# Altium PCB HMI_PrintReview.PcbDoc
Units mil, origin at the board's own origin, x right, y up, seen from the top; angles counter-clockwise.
Board outline 3135 x 2040 mil, 2 copper layers (Top Layer, Bottom Layer); 24 components, 26 nets, 141 pads, 13 vias.
Unrouted connection lines stored in the file: 1.
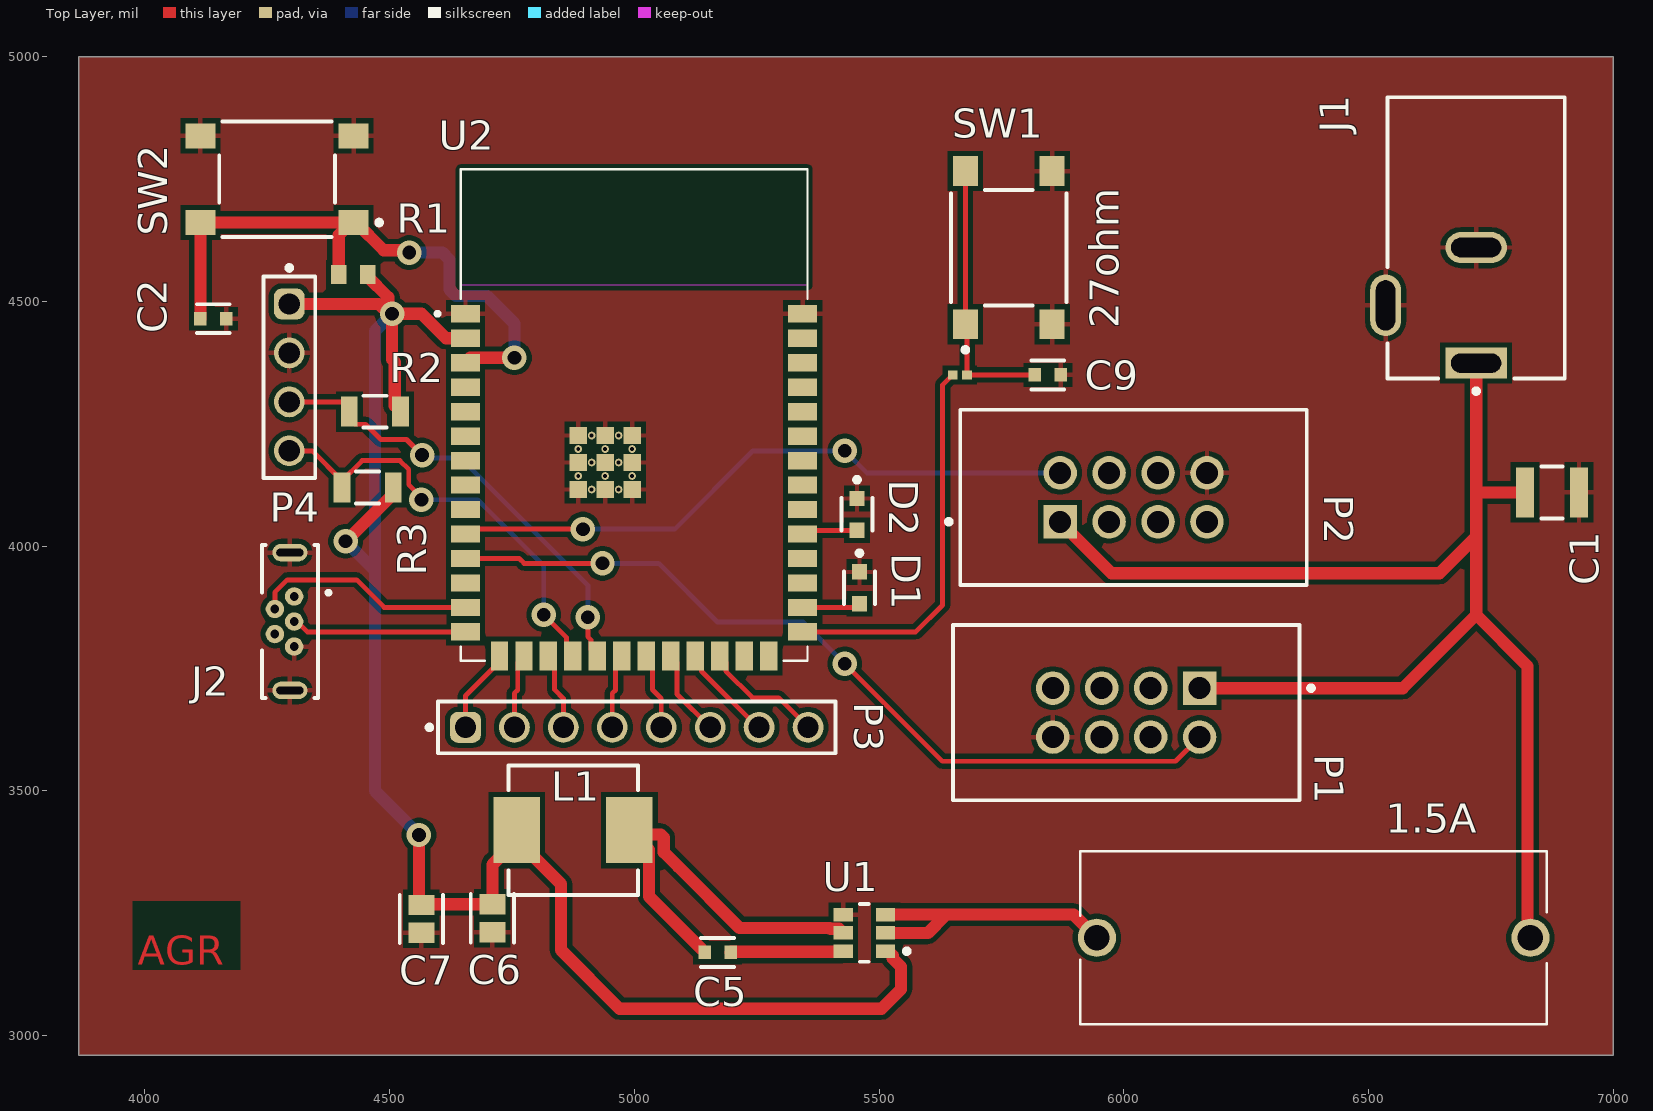
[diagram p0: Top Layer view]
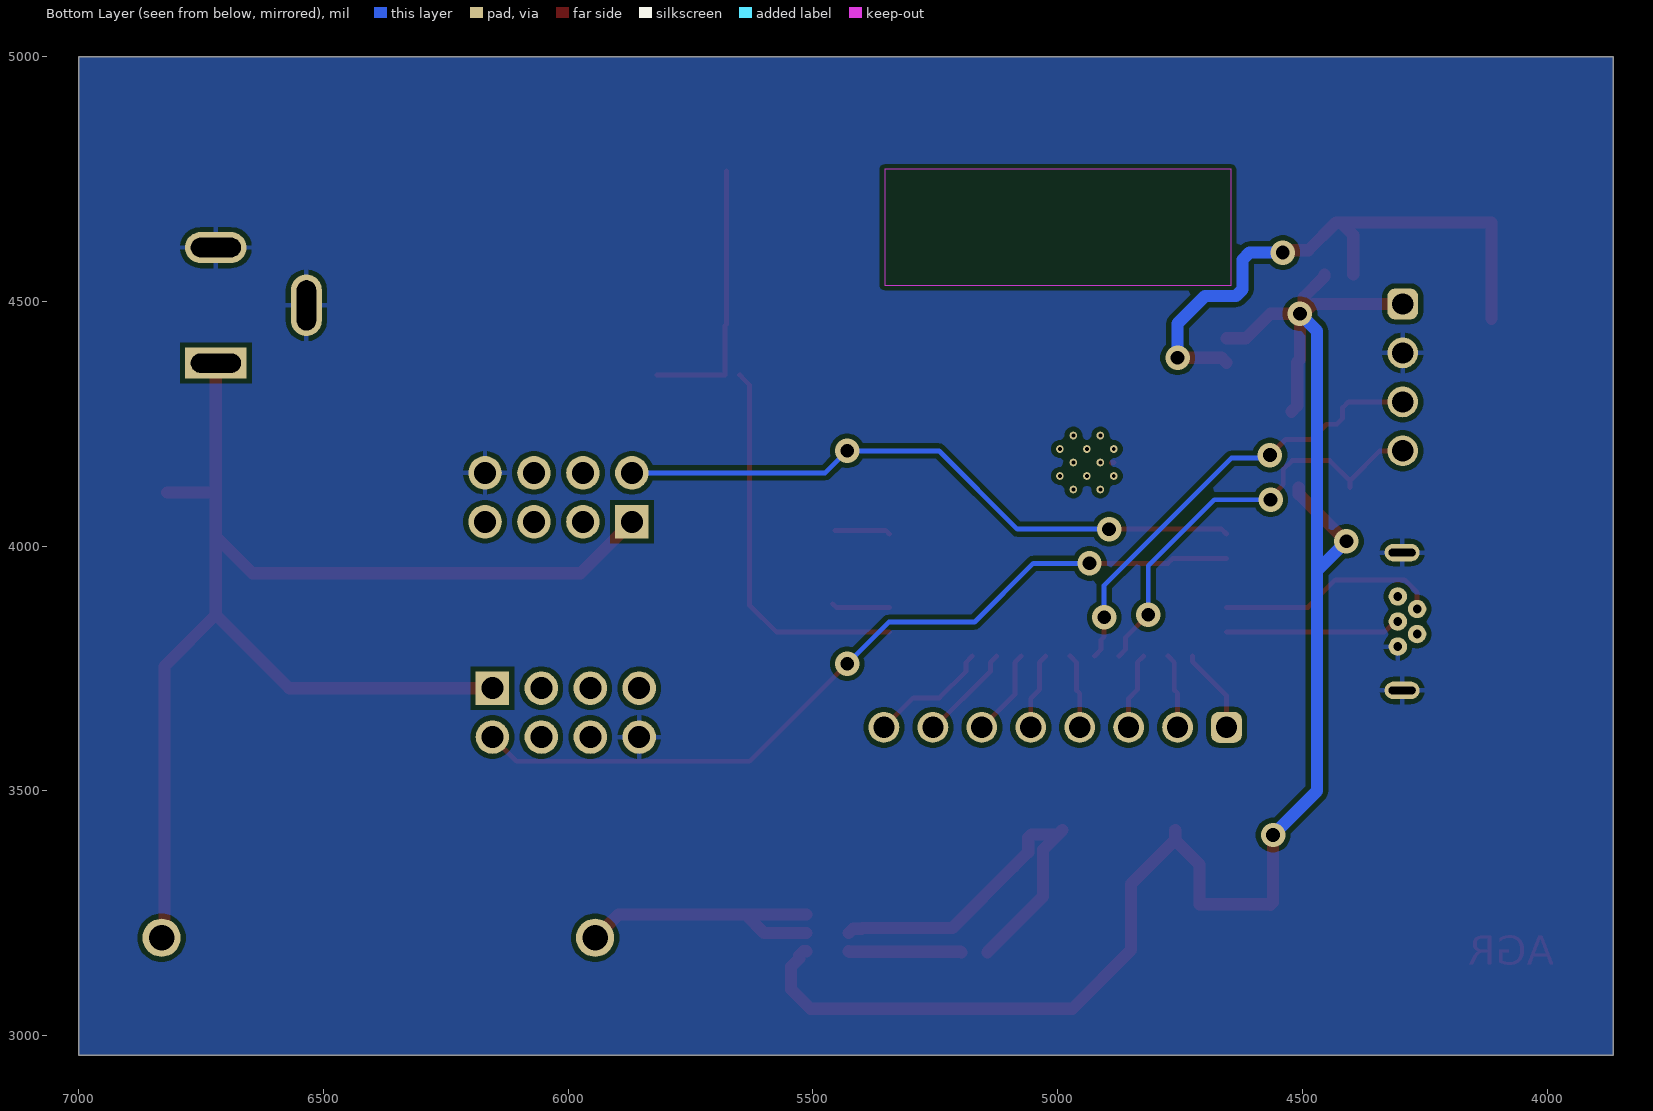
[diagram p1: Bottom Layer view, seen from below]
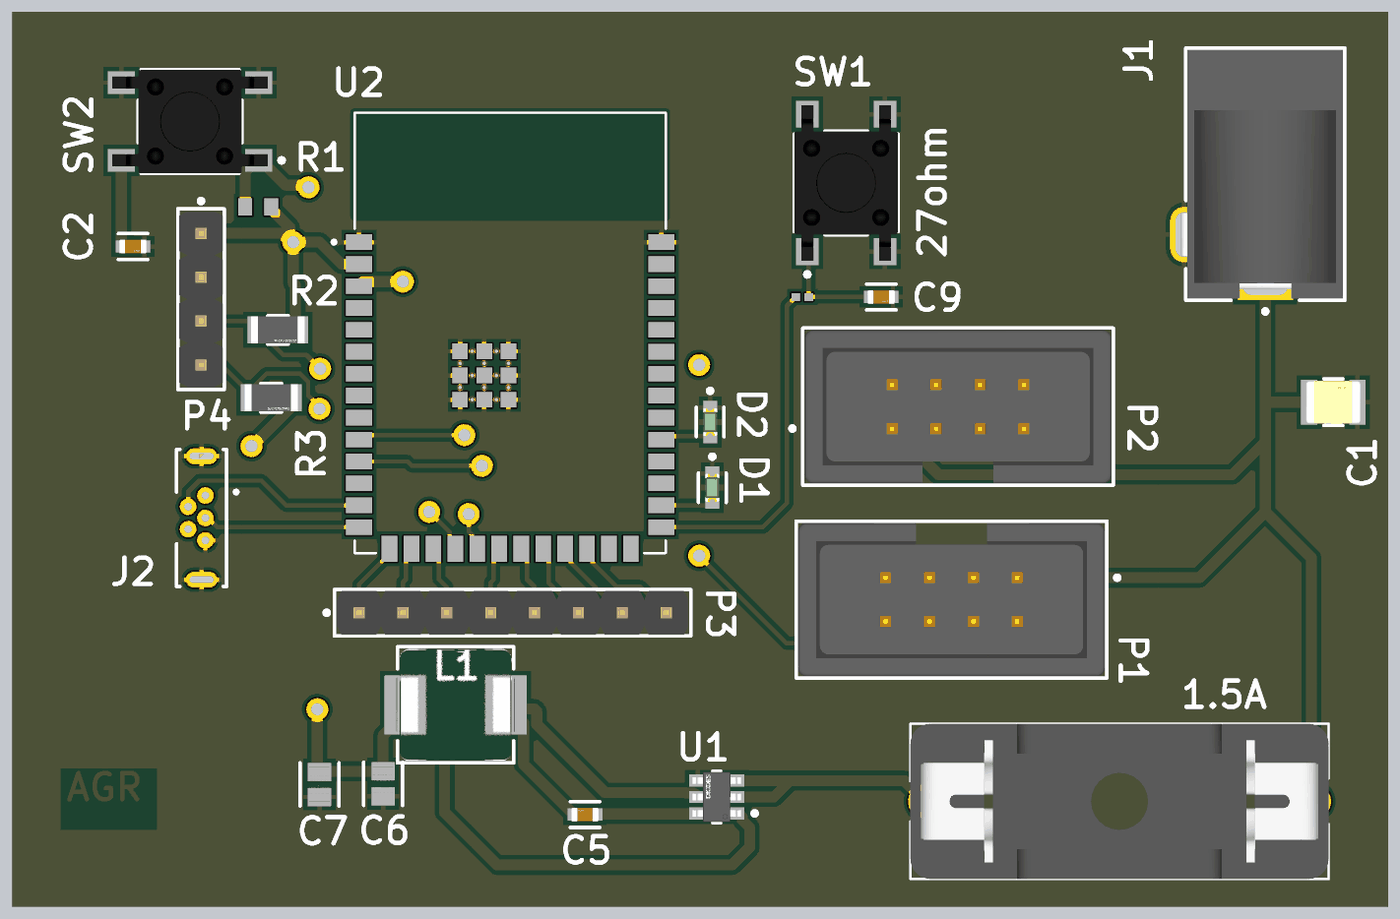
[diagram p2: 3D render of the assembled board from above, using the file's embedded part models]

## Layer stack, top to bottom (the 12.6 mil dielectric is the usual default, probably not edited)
Top Solder: solder mask 0.4, Solder Resist, Dk 3.5
Top Layer: signal copper 1.4
Dielectric 1: dielectric 12.6, FR-4, Dk 4.8
Bottom Layer: signal copper 1.4
Bottom Solder: solder mask 0.4, Solder Resist, Dk 3.5

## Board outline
3865,2960 3865,5000 7000,5000 7000,2960

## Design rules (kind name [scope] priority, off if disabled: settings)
Clearance [All] p1: gap=10 ignorepadtopadclearanceinfootprint=FALSE
PolygonConnect [All] p1: connectstyle=Relief reliefconductorwidth=10 reliefentries=4 polygonreliefangle="90 Angle" airgapwidth=10
RoutingVias [All] p1: holewidth=28 width=50 viastyle="Through Hole" minholewidth=28 minwidth=50 maxholewidth=28 maxwidth=50
SolderMaskExpansion [All] p1: expansion=4 istentingtop=FALSE
SupplyNets "Schematic Supply Nets_1" [InNet('GND')] p1: voltage=0.000
SupplyNets "Schematic Supply Nets" [InNet('+3.3')] p2: voltage=0.000
Width [All] p1: maxlimit=10 minlimit=10 preferedwidth=10
30 further rules are at their usual default settings.

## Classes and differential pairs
net class GND: GND

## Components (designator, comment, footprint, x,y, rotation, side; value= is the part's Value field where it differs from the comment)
1.5A "4628" 4628-Footprint-1 6830.83,3200 r180 top
27ohm "RC0402FR-0727RL" RESC1005X40X25LL05T10 5665,4350 r180 top
C1 "10uF" FP-C1210C106M6PACTU-MFG 6875,4110 r0 top
C2 "GRM188R72A104KA35D" FP-GRM188-0_1-e0_2_0_5-MFG 4140,4465 r0 top
C5 "GRM188R72A104KA35D" FP-GRM188-0_1-e0_2_0_5-MFG 5170,3170 r180 top
C6 "CL21A226MOCLRNC" FP-CL21-IPC_C 4710,3240 r270 top
C7 "CL21A226MOCLRNC" FP-CL21-IPC_C 4565,3238.57 r270 top
C9 "GRM188R72A104KA35D" FP-GRM188-0_1-e0_2_0_5-MFG 5845,4350 r0 top
D1 "SML-D12U8WT86C" FP-SML-D12-MFG 5460,3915 r270 top
D2 "SML-D12U8WT86C" FP-SML-D12-MFG 5455,4065 r270 top
J1 "PJ-102A" FP-PJ-102A-MFG 6720,4630 r0 top
J2 "USB3131-30-0230-A_REVB" GCT_USB3131-30-0230-A_REVB 4296.34,3846.18 r270 top
L1 "4.7uH" FP-IHLP-2525EZ-FP_2_413x3-MFG 4875,3420 r180 top
P1 "70246-0801" FP-0702460801-MFG 6005,3660 r180 top
P2 "70246-0801" FP-0702460801-MFG 6020,4100 r0 top
P3 "Conn 01x08" 61300811121 5005,3630 r0 top
P4 "01x04" 61300411121 4295,4345 r270 top
R1 "RC0603JR-0710KL" RESC1608X55X25ML10T15 4425.47,4555 r0 top
R2 "10k 0.25W" FP-CR1206-IPC_C 4470,4275 r0 top value=10kR
R3 "10k 0.25W" FP-CR1206-IPC_C 4455,4120 r0 top value=10kR
SW1 "PTS645SH50SMTR92LFS" FP-PTS645SH50SMTR92LFS-MFG 5765,4610 r90 top
SW2 "PTS645SH50SMTR92LFS" FP-PTS645SH50SMTR92LFS-MFG 4270,4750 r180 top
U1 "AP63203WU-7" FP-TSOT26-MFG 5470,3210 r180 top
U2 "ESP32-S3-WROOM-1-N4" XCVR_ESP32-S3-WROOM-1-N4 4999.49,4267.91 r0 top

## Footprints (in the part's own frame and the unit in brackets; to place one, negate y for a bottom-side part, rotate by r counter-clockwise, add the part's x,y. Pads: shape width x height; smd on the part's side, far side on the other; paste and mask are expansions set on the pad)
4628-Footprint-1 [mm]
  round 1.98 hole 1.32: 1(0,0) 2(22.5,0)
  silkscreen extent -0.85,-4.49 23.36,4.49, body extent -0.85,-4.5 23.35,4.5, height 11.99
61300411121 [mm] "Pin Header, pitch 2.54 mm, THT, Vertical, single row, 4p"
  rrect50% 1.6x1.6 hole 1.1: 1(-3.81,0)
  round 1.6 hole 1.1: 2(-1.27,0) 3(1.27,0) 4(3.81,0)
  silkscreen extent -5.8,-1.35 5.23,1.35, body extent -5.08,-1.27 5.08,1.27, height 8.57
61300811121 [mm] "Pin Header, pitch 2.54 mm, THT, Vertical, single row, 8p"
  rrect50% 1.6x1.6 hole 1.1: 1(-8.89,0)
  round 1.6 hole 1.1: 2(-6.35,0) 3(-3.81,0) 4(-1.27,0) 5(1.27,0) 6(3.81,0) 7(6.35,0) 8(8.89,0)
  silkscreen extent -10.88,-1.35 10.31,1.35, body extent -10.16,-1.27 10.16,1.27, height 8.57
FP-0702460801-MFG [mm]
  rect 1.74x1.74 hole 1.14 paste-2539.97 mask+0: 1(-3.81,-1.27)
  round 1.74 hole 1.14 paste-2539.97 mask+0: 2(-3.81,1.27) 3(-1.27,-1.27) 4(-1.27,1.27) 5(1.27,-1.27) 6(1.27,1.27) 7(3.81,-1.27) 8(3.81,1.27)
  silkscreen extent -9.72,-4.54 8.99,4.54, body extent -9.09,-4.64 9.09,4.64, height 0.25
FP-C1210C106M6PACTU-MFG [mm]
  rect 0.95x2.6 smd paste+0 mask+0: 1(-1.4,0) 2(1.4,0)
  silkscreen extent -0.55,-1.35 0.55,1.35, body extent -1.97,-1.45 1.97,1.45, height 0.25
FP-CL21-IPC_C [mil]
  rect 41.52x53.39 smd paste+0 mask+0: 1(-28.57,0) 2(28.57,0)
  silkscreen extent -49,-44 49,44, body extent -53,-32 53,32, height 10
FP-CR1206-IPC_C [mil]
  rect 33.79x61.5 smd paste+0 mask+0: 1(-52.24,0) 2(52.24,0)
  silkscreen extent -24,-32 24,32, body extent -73,-36 73,36, height 10
FP-GRM188-0_1-e0_2_0_5-MFG [mm]
  rect 0.65x0.7 smd paste+0 mask+0: 1(-0.675,0) 2(0.675,0)
  silkscreen extent -0.85,-0.75 0.85,0.75, body extent -1.1,-0.55 1.1,0.55, height 0.25
FP-IHLP-2525EZ-FP_2_413x3-MFG [mil]
  rect 95x135 smd paste+0 mask+0: 1(-115,0) 2(115,0)
  silkscreen extent -132,-132 132,132, body extent -166,-136 166,136, height 10
FP-PJ-102A-MFG [mm]
  rect 3.2x1.6 hole 1 slot 2.6 at 0 deg paste-2539.97 mask+0: 1(0,-6.5)
  rrect100% 3.2x1.6 hole 1 slot 2.6 at 0 deg paste-2539.97 mask+0: 2(0,-0.5)
  rrect100% 1.6x3.2 hole 2.6 slot 1 at 0 deg paste-2539.97 mask+0: 3(-4.7,-3.5)
  silkscreen extent -4.6,-8.07 4.6,7.3, body extent -5.6,-7.4 4.7,7.4, height 0.25
FP-PTS645SH50SMTR92LFS-MFG [mm]
  rect 1.55x1.3 smd paste+0 mask+0: 1(-3.975,2.25) 2(3.975,2.25) 3(-3.975,-2.25) 4(3.975,-2.25)
  silkscreen extent -5.42,-3 3,3, body extent -4.85,-3.1 4.85,3.1, height 0.25
FP-SML-D12-MFG [mm]
  rect 0.8x0.8 smd paste+0 mask+0: 1(-0.825,0) 2(0.825,0)
  silkscreen extent -1.92,-0.8 0.85,0.8, body extent -1.33,-0.55 1.33,0.55, height 0.25
FP-TSOT26-MFG [mm]
  rect 1x0.7 smd paste+0 mask+0: 1(-1.099,0.95) 2(-1.099,0) 3(-1.099,-0.95) 4(1.099,-0.95) 5(1.099,0) 6(1.099,0.95)
  silkscreen extent -2.33,-1.5 0.22,1.5, body extent -1.7,-1.6 1.7,1.6, height 0.25
GCT_USB3131-30-0230-A_REVB [mm]
  round 0.958 hole 0.45: 1(-1.3,0.22) 2(-0.65,-0.78) 3(0,0.22) 4(0.65,-0.78) 5(1.3,0.22)
  oval 0.908x1.816 hole 0.4 slot 1.4 at 90 deg: S1(-3.575,0) S2(3.575,0)
  silkscreen extent -3.97,-1.45 3.97,2.1
RESC1005X40X25LL05T10 [mm] "Chip Resistor, 2-Leads, Body 1.00x0.50mm, IPC High Density"
  rect 0.5x0.45 smd: 1(-0.375,0) 2(0.375,0)
  body extent -0.53,-0.27 0.53,0.28, height 0.4
RESC1608X55X25ML10T15 [mm] "Chip Resistor, 2-Leads, Body 1.60x0.80mm, IPC Low Density"
  rect 0.8x1 smd: 1(-0.75,0) 2(0.75,0)
  body extent -0.85,-0.45 0.85,0.45, height 0.55
XCVR_ESP32-S3-WROOM-1-N4 [mm]
  rect 1.5x0.9 smd: 1(-8.75,5.26) 2(-8.75,3.99) 3(-8.75,2.72) 4(-8.75,1.45) 5(-8.75,0.18) 6(-8.75,-1.09) 7(-8.75,-2.36) 8(-8.75,-3.63) 9(-8.75,-4.9) 10(-8.75,-6.17) 11(-8.75,-7.44) 12(-8.75,-8.71) 13(-8.75,-9.98) 14(-8.75,-11.25) 27(8.75,-11.25) 28(8.75,-9.98) 29(8.75,-8.71) 30(8.75,-7.44) 31(8.75,-6.17) 32(8.75,-4.9) 33(8.75,-3.63) 34(8.75,-2.36) 35(8.75,-1.09) 36(8.75,0.18) 37(8.75,1.45) 38(8.75,2.72) 39(8.75,3.99) 40(8.75,5.26)
  rect 0.9x1.5 smd: 15(-6.985,-12.5) 16(-5.715,-12.5) 17(-4.445,-12.5) 18(-3.175,-12.5) 19(-1.905,-12.5) 20(-0.635,-12.5) 21(0.635,-12.5) 22(1.905,-12.5) 23(3.175,-12.5) 24(4.445,-12.5) 25(5.715,-12.5) 26(6.985,-12.5)
  rect 0.9x0.9 smd: 41_1(-1.5,-2.46) 41_2(-2.9,-2.46) 41_3(-0.1,-2.46) 41_4(-2.9,-3.86) 41_5(-1.5,-3.86) 41_6(-0.1,-3.86) 41_7(-2.9,-1.06) 41_8(-1.5,-1.06) 41_9(-0.1,-1.06)
  round 0.4 hole 0.2 mask+0: 41_10(-1.5,-1.76) 41_11(-2.9,-1.76) 41_12(-0.1,-1.76) 41_13(-2.9,-3.16) 41_14(-1.5,-3.16) 41_15(-0.1,-3.16) 41_16(-2.2,-1.06) 41_17(-0.8,-1.06) 41_18(-2.2,-2.46) 41_19(-0.8,-2.46) 41_20(-2.2,-3.86) 41_21(-0.8,-3.86)
  Keep-Out Layer region: 9,6.75 -9,6.75 -9,12.75 9,12.75
  Keep-Out Layer region: 9,6.75 -9,6.75 -9,12.75 9,12.75
  silkscreen extent -10.3,-12.75 9,12.75

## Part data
1.5A: library part CMP-00029-1, "Fuses/Accessories"
27ohm: library part CMP-2002-07055-1, Manufacturer="Yageo / Phycomp"
C1: library part CMP-1038-02235-2, "CAP CER 10UF 35V X5R 1210", Case Code (Imperial)=1210, Case Code (Metric)=3225, Dielectric=X5R, Dielectric Material=Ceramic, Max Operating Temperature=85°C, Min Operating Temperature=-55°C, Package Quantity=2000, Tolerance=20%, Voltage=35V
C2 C5 C9: library part CMP-1035-02595-8, "Chip Multilayer Ceramic Capacitors for General Purpose, 0603, 0.10uF, X7R, 15%, 10%, 100V", Capacitance=100nF, Case Code (Imperial)=0603, Case Code (Metric)=1608, Dielectric=X7R, Max Operating Temperature=125°C, Min Operating Temperature=-55°C, Package Quantity=1, Tolerance=10%, Voltage=100V
C6 C7: library part CMP-13271-002990-1, "CL21 Series 0805 22uF 16V ±20% Tolerance X5R Multilayer Ceramic Chip Capacitor", Capacitance=22uF, Case Code (Imperial)=0805, Case Code (Metric)=2012, Max Operating Temperature=85°C, Min Operating Temperature=-55°C, Tolerance=20%, Voltage Rating=16V
D1 D2: library part CMP-08952-000014-1, "LED RED 1608 SMD", Colour=Red, Forward Current=20mA, Forward Voltage=2.2V, Manufacturer=Rohm, Package=SML-D12, Power Dissipation=54mW, Reverse Voltage=5V, Temperature="-40°C to +85°C", Temperature Range High=+85°C, Temperature Range Low=-40°C
J1: library part CMP-00031-1, "2.0 x 6.5 mm, 2.5 A, Horizontal, Through Hole, Tapered Pins, Dc Power Jack Connector"
J2: library part CMP-008-000000-2, "USB - micro B USB 2.0 Receptacle Connector 5 Position Through Hole", Package=None
L1: library part CMP-00011-1, "General Purpose Inductor, 4.7uH, 20%, 1 Element, Composite-Core, SMD, 2525", Case/Size Code=2726, DC Resistance (DCR)=30.3mR, Inductor Application="HIGH CURRENT INDUCTOR", Inductor Type="GENERAL PURPOSE INDUCTOR", Max Current Rating=6.5A, Max Operating Temperature=125°C, Min Operating Temperature=-55°C, Package Height=5mm, Package Length=6.86mm, Package Style=SMTMeter, Package Width=6.47mm, Test Frequency=100kHz, Tolerance=20%
P1 P2: library part CMP-00034-1, "Board Connector, 8 Contact(s), 2 Row(s), Male, Straight, 0.1 inch Pitch, Solder Terminal, Guide Slot, Black Insulator, Receptacle", Dielectric Withstanding Voltage (AC)=900V, Flammability Rating="UL94 V-0", Insulation Color=Black, Insulation Resistance=12GR, Manufacturer Series=70246, Max Operating Temperature=120°C, Min Operating Temperature=-55°C, Rated Current (Signal)=2.5A
P3: library part CMP-00017-1, "Board Connector, 8 Contact(s), 1 Row(s), Male, Straight, 0.1 inch Pitch, Solder Terminal, Locking, Black Insulator, Plug", Contact Resistance=20mR, Dielectric Withstanding Voltage (AC)=500V, Insulation Color=Black, Insulation Resistance=1GR, Manufacturer Series=613, Max Operating Temperature=125°C, Min Operating Temperature=-40°C, Rated Current (Signal)=3A
P4: library part CMP-00044-1, "Board Connector, 4 Contact(s), 1 Row(s), Male, Straight, 0.1 inch Pitch, Solder Terminal, Locking, Black Insulator, Plug", Contact Resistance=20mR, Dielectric Withstanding Voltage (AC)=500V, Insulation Color=Black, Insulation Resistance=1GR, Max Operating Temperature=125°C, Min Operating Temperature=-40°C, Rated Current (Signal)=3A
R1: library part CMP-2000-05022-1, "Resistor, 10 KOhm, +/- 5%, 100 mW, -55 to 155 degC, 0603 (1608 Metric), RoHS, Tape and Reel", Case Code - in=0603, Case Code - mm=1608, Manufacturer=Yageo, Operating Temperature Range=-55Cto+155C, Package Description="2-Pin Surface Mount Device, Body 1.6 x 0.8 mm", Package Reference=603, Power Rating=100mW, Resistance=10kOhms, Temperature Coefficient=100PPM/C, Tolerance=5%, Voltage Rating=50V
R2 R3: library part CMP-00022-2, "Fixed Resistor, Metal Glaze/thick Film, 0.25W, 10000ohm, 200V, 5% +/-Tol, 200ppm/Cel, Surface Mount, 1206", Case/Package=1206, Max Operating Temperature=155°C, Min Operating Temperature=-55°C, Package Height=0.6mm, Package Length=3.2mm, Package Shape=Rectangular, Package Width=1.6mm, Power=250mW, Rated Temperature=70°C, Resistor Type="FIXED RESISTOR", Temperature Coefficient (ppm/Cel)=200, Tolerance=5%, Working Voltage=200V
SW1 SW2: library part CMP-10040-000028-1, "SWITCH TACTILE SPST-NO 0.05A 12V", Case/Package=SMD/SMT, Color=Black, Current Rating=50mA, Max Operating Temperature=60°C, Max Voltage Rating (DC)=12V, Min Operating Temperature=-20°C, Operating Force=200gf, Package Quantity=1000
U1: library part CMP-12757-000006-1, "IC REG BUCK 3.3V 2A TSOT26", Ambient Temperature Range High=+85°C, Ambient Temperature Range Low=-40°C, Manufacturer="Diodes Inc.", Max Junction Temp=+160°C, Max Supply Voltage=32V, Min Supply Voltage=3.8V, Nominal Supply Current=22uA, Output Current=2A, Output Voltage=3.3V, Package=TSOT26, Switching Frequency=1.1MHz, Temperature="to +160°C"
U2: library part CMP-002-000002-1, Package=None

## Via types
v1: diameter 50, hole 28, Top Layer to Bottom Layer, 13 vias

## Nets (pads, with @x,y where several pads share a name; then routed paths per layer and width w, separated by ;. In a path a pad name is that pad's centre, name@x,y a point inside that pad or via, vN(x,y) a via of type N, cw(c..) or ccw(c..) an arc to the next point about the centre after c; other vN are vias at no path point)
+3.3: C6.1 C7.1 L1.2 P4.1 R1.2 R2.2 R3.2 U1.1 U2.2 | length 3626.6
  Top Layer w10: 4505,4381.31 4510.35,4375.96 ; C7.1@4560,3272.15 C7.1
  Top Layer w25: P4.1 4478.24,4495 4498.24,4475 v1(4505,4475) ; v1@4411.1,4010 4507.24,4106.14 R3.2 ; R1.2 4455,4551.06 4497.35,4508.72 4497.35,4482.65 v1(4505,4475) ; 4505,4381.31 v1(4505,4475) ; 4510.35,4375.96 4510.35,4286.89 R2.2 ; C7.1@4560,3272.15 v1(4560,3410) ; C7.1 4566.43,3268.57 C6.1 4710,3350 L1.2@4760,3400 ; U2.2 4615,4425 4565,4475 v1(4505,4475) ; L1.2 L1.2@4760,3400 ; U1.1 5519.19,3172.6 5527.97,3163.82 5527.97,3157.91 5545,3140.89 5545,3095 5505,3055 4970,3055 4850,3175 4850,3310 L1.2@4760,3400
  Bottom Layer w10: 4465,3955 4470,3955
  Bottom Layer w25: v1(4410,4010) 4465,3955 ; v1(4505,4475) 4470,4440 4470,3955 4470,3500 v1(4560,3410)
C1: P3.1 U2.15 | length 174.6
  Top Layer w10: P3.1 4655,3694.49 4724.49,3763.98 U2.15
C2: P3.2 U2.16 | length 153.9
  Top Layer w10: P3.2 4755,3699.48 4761.77,3706.26 4761.77,3763.07 U2.16
C3: P3.3 U2.17 | length 158.4
  Top Layer w10: U2.17 4837.2,3763.07 4837.2,3706.7 4855,3688.9 P3.3
C4: P3.4 U2.20 | length 153.9
  Top Layer w10: P3.4 4955,3699.48 4961.77,3706.26 4961.77,3763.07 U2.20
EN: C2.1 R1.1 SW2.1 SW2.2 U2.3 | length 1262.4
  Top Layer w25: C2.1 SW2.2@4113.43,4661.34 ; SW2.2 SW2.1 ; R1.1 4395.94,4635.79 4421.57,4661.42 SW2.1 ; v1(4540,4600) 4535.22,4604.78 4488.05,4604.78 4431.42,4661.42 SW2.1 ; U2.3@4660.14,4380.14 U2.3 4665,4385 v1(4755,4385)
  Bottom Layer w25: v1(4540,4600) 4608.01,4600 4622.66,4585.36 4622.66,4524.34 4635.84,4511.16 4698.84,4511.16 4755,4455 v1(4755,4385)
GND: C1.2 C2.2 C6.2 C7.2 C9.2 D1.1 D2.1 J1.2 J1.3 J2.5 J2.S1 J2.S2 P1.8 P2.8 P4.2 SW1.3 SW1.4 SW2.3 SW2.4 U1.4 U2.1 U2.40 U2.41_1 U2.41_2 U2.41_3 U2.41_4 U2.41_5 U2.41_6 U2.41_7 U2.41_8 U2.41_9 | length 5.1
  Top Layer w10: U2.41_2 4888.94,4171.06 U2.41_2@4890,4170
GPIO0: 27ohm.2 U2.27 | length 787.8
  Top Layer w10: U2.27 5575,3825 5630,3880 5630,4329.76 5645.39,4345.16 5645.39,4346.14 5649.25,4350 27ohm.2
Net1.5A_1: 1.5A.1 C1.1 J1.1 P1.1 P2.1 | length 2871.6
  Top Layer w25: P2.1 5975,3945 6645,3945 6720,4020 ; P1.1 6570,3710 6720,3860 ; J1.1 6720,4110 ; C1.1 6720,4110 ; 1.5A.1 6825,3205.83 6825,3755 6720,3860 ; 6720,3860 6720,4020 ; 6720,4020 6720,4110
Net1.5A_2: 1.5A.2 U1.2 U1.3 | length 590
  Top Layer w25: U1.2 5600,3210 5635,3245 5635,3247.4 ; U1.3 5635,3247.4 ; 1.5A.2 5897.6,3247.4 5635,3247.4
Net27ohm_1: 27ohm.1 C9.1 SW1.1 SW1.2 | length 556.5
  Top Layer w10: SW1.2 SW1.1 5679.76,4450.16 27ohm.1 C9.1
NetC5_1: C5.1 U1.6 | length 231.2
  Top Layer w25: C5.1 5197.87,3171.3 5425.41,3171.3 U1.6
NetC5_2: C5.2 L1.1 U1.5 | length 841.9
  Top Layer w25: L1.1 5030,3380 5030,3284.41 5143.43,3170.98 C5.2 ; L1.1@4999.14,3410.86 5054.14,3410.86 5060,3405 5060,3375 5090,3345 5215,3220 5399.44,3220 5400.81,3218.62 5418.09,3218.62 U1.5
NetD1_2: D1.2 U2.28 | length 119.1
  Top Layer w10: U2.28 5452.48,3875 D1.2
NetD2_2: D2.2 U2.31 | length 114.1
  Top Layer w10: U2.31 5351.5,4032.52 D2.2
NetJ2_2: J2.2 U2.13 | length 457.3
  Top Layer w10: J2.2 4265.63,3905.87 4290.98,3931.22 4432.61,3931.22 4488.83,3875 U2.13
NetJ2_3: J2.3 U2.14 | length 358.8
  Top Layer w10: J2.3 4310.52,3846.18 4331.7,3825 U2.14
NetP1_1: 
R1: P3.5 U2.21 | length 158.4
  Top Layer w10: U2.21 5037.2,3763.07 5037.2,3706.7 5055,3688.9 P3.5
R2: P3.6 U2.22 | length 179.1
  Top Layer w10: U2.22 5087.2,3763.07 5087.2,3697.8 P3.6
R3: P3.7 U2.23 | length 201.7
  Top Layer w10: U2.23 5137.2,3763.07 5137.2,3744.61 5251.82,3630 P3.7
R4: P3.8 U2.24 | length 251.7
  Top Layer w10: U2.24 5187.2,3763.07 5187.2,3744.61 5241.73,3690.09 5294.91,3690.09 P3.8
SCL: P4.3 R2.1 U2.19 | length 930.5
  Top Layer w10: P4.3 4405.86,4295 4417.76,4283.11 R2.1 4417.76,4261.14 4429.65,4249.25 4450.85,4249.25 4482.07,4218.04 4534.63,4218.04 v1(4566.33,4186.33) ; v1(4905,3855) 4905,3815 4911.77,3808.23 4911.77,3788.5 U2.19
  Bottom Layer w10: v1(4566.33,4186.33) 4572.67,4180 4645,4180 4905,3920 v1(4905,3855)
SDA: P4.4 R3.1 U2.18 | length 895.3
  Top Layer w10: P4.4 4341.61,4195 R3.1@4402.76,4133.86 ; R3.1 R3.1@4402.76,4133.86 ; v1(4565,4095) 4565,4099.84 4539.14,4125.7 4539.14,4156.96 4521.1,4175 4443.9,4175 R3.1@4402.76,4133.86 ; v1(4815,3860) 4861.77,3813.23 4861.77,3788.5 U2.18
  Bottom Layer w10: v1(4565,4095) 4680,4095 4815,3960 v1(4815,3860)
UART_RX: P1.2 U2.11 | length 1692
  Top Layer w10: U2.11 4765,3975 4775,3965 v1(4935,3965) ; v1(5430,3760) 5629.25,3560.75 6105.75,3560.75 P1.2
  Bottom Layer w10: v1(4935,3965) 5050,3965 5170,3845 5345,3845 v1(5430,3760)
UART_TX: P2.2 U2.10 | length 1304.1
  Top Layer w10: U2.10 4665,4035 v1(4895,4035)
  Bottom Layer w10: v1(4895,4035) 5082.5,4035 5242.5,4195 v1(5430,4195) 5475,4150 P2.2
pads on no net: J2.1 J2.4 P1.3 P1.4 P1.5 P1.6 P1.7 P2.3 P2.4 P2.5 P2.6 P2.7 U2.4 U2.5 U2.6 U2.7 U2.8 U2.9 U2.12 U2.25 U2.26 U2.29 U2.30 U2.32 U2.33 U2.34 U2.35 U2.36 U2.37 U2.38 U2.39 U2.41_10 U2.41_11 U2.41_12 U2.41_13 U2.41_14 U2.41_15 U2.41_16 U2.41_17 U2.41_18 U2.41_19 U2.41_20 U2.41_21

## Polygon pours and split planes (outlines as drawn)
GND on Bottom Layer "GND_L02_P001" (solid, pour order 1): 3865,5000 3865,2960 7000,2960 7000,5000
GND on Top Layer "GND_L01_P000" (solid, pour order 0): 3865,5000 7000,5000 7000,2955 6995,2960 3865,2960

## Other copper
Top Layer:
  text "AGR" at 3985,3145 h60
